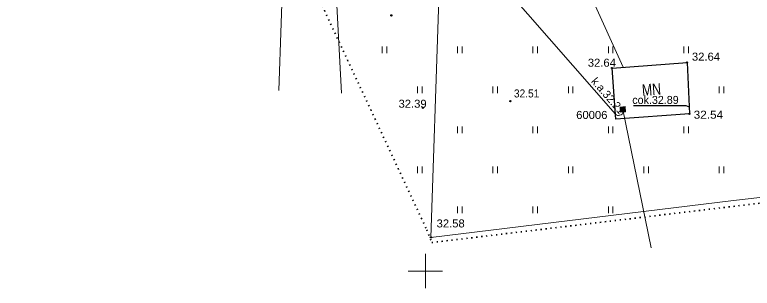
# Model space of a CAD drawing. Extents: x 380758 to 381729, y 283236 to 283533.
# Drawn here: x 381364.1 to 381428.6, y 283298.5 to 283322.4 of the extents above; entities that cross this region are included whole.
import ezdxf

# ---------------------------------------------------------------- set-up
doc = ezdxf.new("R2010")
doc.units = 0
doc.header["$LTSCALE"] = 0.28
doc.linetypes.add('DOTTED', pattern=[1.5, 0.3, -1.2])
for name, color, linetype, lineweight in [('18', 7, 'Continuous', 13), ('23', 7, 'Continuous', 13), ('25', 7, 'DOTTED', 35), ('30', 7, 'Continuous', 13), ('35', 7, 'Continuous', 13), ('4', 7, 'Continuous', 13), ('40', 7, 'Continuous', 25), ('42', 7, 'Continuous', 13), ('58', 7, 'Continuous', 25), ('7', 7, 'Continuous', 13), ('9', 7, 'Continuous', 13)]:
    doc.layers.add(name, color=color, linetype=linetype, lineweight=lineweight)

msp = doc.modelspace()

# ---------------------------------------------------------------- hatches: boundary and pattern name
at = {"layer": '18'}
msp.add_hatch(color=256, dxfattribs=at).paths.add_polyline_path([(381417.465, 283314.397), (381417.503, 283313.952), (381417.065, 283313.915), (381417.027, 283314.36)])

# ---------------------------------------------------------------- linework, layer by layer
for points in [[(381387.166, 283315.811), (381387.57, 283327.619), (381388.084, 283336.585)], [(381391.392, 283336.674), (381392.001, 283327.681), (381392.649, 283315.586)]]:
    msp.add_lwpolyline(points, dxfattribs=at)
msp.add_lwpolyline([(381417.465, 283314.397), (381417.503, 283313.952), (381417.065, 283313.915), (381417.027, 283314.36)], close=True, dxfattribs=at)
at = {"layer": '23'}
for p, q in [((381396.209, 283319.066), (381396.209, 283319.666)), ((381396.609, 283319.066), (381396.609, 283319.666)), ((381402.809, 283319.066), (381402.809, 283319.666)), ((381403.209, 283319.066), (381403.209, 283319.666)), ((381409.409, 283319.066), (381409.409, 283319.666)), ((381409.809, 283319.066), (381409.809, 283319.666)), ((381416.009, 283319.066), (381416.009, 283319.666)), ((381416.409, 283319.066), (381416.409, 283319.666)), ((381422.609, 283319.066), (381422.609, 283319.666)), ((381423.009, 283319.066), (381423.009, 283319.666)), ((381399.309, 283315.566), (381399.309, 283316.166)), ((381399.709, 283315.566), (381399.709, 283316.166)), ((381405.909, 283315.566), (381405.909, 283316.166)), ((381406.309, 283315.566), (381406.309, 283316.166)), ((381412.509, 283315.566), (381412.509, 283316.166)), ((381412.909, 283315.566), (381412.909, 283316.166)), ((381425.709, 283315.566), (381425.709, 283316.166)), ((381426.109, 283315.566), (381426.109, 283316.166)), ((381402.809, 283312.066), (381402.809, 283312.666)), ((381403.209, 283312.066), (381403.209, 283312.666)), ((381409.409, 283312.066), (381409.409, 283312.666)), ((381409.809, 283312.066), (381409.809, 283312.666)), ((381416.009, 283312.066), (381416.009, 283312.666)), ((381416.409, 283312.066), (381416.409, 283312.666)), ((381422.609, 283312.066), (381422.609, 283312.666)), ((381423.009, 283312.066), (381423.009, 283312.666)), ((381399.309, 283308.566), (381399.309, 283309.166)), ((381399.709, 283308.566), (381399.709, 283309.166)), ((381405.909, 283308.566), (381405.909, 283309.166)), ((381406.309, 283308.566), (381406.309, 283309.166)), ((381412.509, 283308.566), (381412.509, 283309.166)), ((381412.909, 283308.566), (381412.909, 283309.166)), ((381419.109, 283308.566), (381419.109, 283309.166)), ((381419.509, 283308.566), (381419.509, 283309.166)), ((381425.709, 283308.566), (381425.709, 283309.166)), ((381426.109, 283308.566), (381426.109, 283309.166)), ((381402.809, 283305.066), (381402.809, 283305.666)), ((381403.209, 283305.066), (381403.209, 283305.666)), ((381409.409, 283305.066), (381409.409, 283305.666)), ((381409.809, 283305.066), (381409.809, 283305.666)), ((381416.009, 283305.066), (381416.009, 283305.666)), ((381416.409, 283305.066), (381416.409, 283305.666))]:
    msp.add_line(p, q, dxfattribs=at)
at = {"layer": '25'}
msp.add_lwpolyline([(381358.23, 283334.462), (381389.309, 283326.777), (381400.12, 283303.606), (381400.55, 283302.499), (381429.749, 283306.005), (381435.528, 283310.373), (381433.049, 283340.868), (381456.224, 283341.607), (381495.519, 283344.123), (381528.407, 283346.153)], dxfattribs=at)
at = {"layer": '30'}
for points in [[(381400, 283301.5), (381400, 283300), (381400, 283298.5)], [(381398.5, 283300), (381400, 283300), (381401.5, 283300)]]:
    msp.add_lwpolyline(points, dxfattribs=at)
at = {"layer": '35'}
msp.add_line((381426.96, 283306.182), (381429.256, 283306.441), dxfattribs=at)
msp.add_lwpolyline([(381426.96, 283306.182), (381400.48, 283302.952), (381401.803, 283342.89)], dxfattribs=at)
at = {"layer": '40'}
msp.add_lwpolyline([(381416.327, 283317.773), (381422.89, 283318.253), (381423.091, 283313.764), (381416.655, 283313.293)], close=True, dxfattribs=at)
at = {"layer": '42', "lineweight": 25}
msp.add_lwpolyline([(381418.205, 283314.505), (381422.79, 283314.505), (381423.063, 283314.389)], dxfattribs=at)
at = {"layer": '58'}
for centre in [(381397.016, 283322.3821), (381422.89, 283318.2531), (381416.327, 283317.7731), (381399.766, 283314.3001), (381407.433, 283314.8721), (381423.091, 283313.7641), (381400.48, 283302.9521)]:
    msp.add_circle(centre, 0.0534, dxfattribs=at)
at = {"layer": '7'}
for p, q in [((381417.265, 283314.156), (381419.754, 283302.044)), ((381417.265, 283314.156), (381417.288, 283313.973)), ((381417.008, 283313.635), (381416.881, 283313.628))]:
    msp.add_line(p, q, dxfattribs=at)
msp.add_lwpolyline([(381416.639, 283313.73), (381407.089, 283324.656), (381399.011, 283334.242)], dxfattribs=at)
for centre, start, end in [((381416.8645, 283313.9276), 221.15445, 273.24153), ((381416.9907, 283313.9347), 273.24153, 7.27717)]:
    msp.add_arc(centre, 0.3, start, end, dxfattribs=at)
at = {"layer": '9'}
msp.add_line((381409.418, 283335.25), (381417.299, 283317.844), dxfattribs=at)

# ---------------------------------------------------------------- texts
at = {"layer": '4', "width": 0.8}
msp.add_text('MN', height=1, rotation=4.183, dxfattribs=at).set_placement((381418.979, 283315.34))
at = {"layer": '42'}
msp.add_text('cok.32.89', height=0.7, dxfattribs=at).set_placement((381418.097, 283314.634))
at = {"layer": '58'}
for s, width, p in [('32.64', 1.05, (381423.314, 283318.418)), ('32.64', 1.05, (381414.205, 283317.89)), ('32.51', 0.95, (381407.739, 283315.202)), ('32.39', 1.05, (381397.644, 283314.3)), ('32.54', 1.1, (381423.468, 283313.339)), ('32.58', 1.05, (381400.974, 283303.824))]:
    msp.add_text(s, height=0.7, dxfattribs=dict(at, width=width)).set_placement(p)
at = {"layer": '7'}
msp.add_text('k.a.32.21', height=0.7, rotation=311.154, dxfattribs=at).set_placement((381414.452, 283316.57))
at = {"layer": '7', "width": 1.05}
msp.add_text('60006', height=0.7, dxfattribs=at).set_placement((381413.188, 283313.319))

doc.saveas('drawing.dxf')
